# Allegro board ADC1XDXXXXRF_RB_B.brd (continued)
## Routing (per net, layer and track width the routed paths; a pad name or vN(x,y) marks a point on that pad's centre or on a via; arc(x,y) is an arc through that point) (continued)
DID-1: length 67
  TOP w0.102: U1.D10 v1(188.44,87.91) ; U5.U24 v1(136.72,87.74)
  SIG1 w0.102: v1(188.44,87.91) 188.84,87.92 189.18,87.58 189.18,82.55 185.31,78.67 144.72,78.67 136.92,86.47 136.92,87.55 v1(136.72,87.74)
  BOTTOM w0.102: R208.2 187.88,87.48 188.01,87.48 v1(188.44,87.91)
DID-2: length 65.8
  TOP w0.102: v1(133.72,88.76) 133.23,89.25 U5.T20 ; U1.C11 186.55,87.27 v1(187.19,86.63)
  SIG2 w0.102: v1(187.19,86.63) 187.19,86.27 187.91,85.55 187.91,83.47 184.11,79.68 143.26,79.68 140.33,82.6 140.33,83.19 138.36,85.16 135.79,85.16 134.12,86.83 134.12,88.36 v1(133.72,88.76)
DID-3: length 65.8
  TOP w0.102: U1.B12 185.27,86 v1(185.85,85.43) ; U5.T23 v1(136.72,88.75)
  SIG2 w0.102: v1(136.72,88.75) 136.72,88.75 137.12,88.35 137.12,86.13 137.37,85.88 139.57,85.88 139.67,85.78 139.67,84.92 139.89,84.7 140.26,84.7 140.48,84.92 140.48,85.78 140.58,85.88 141.14,85.88 141.29,85.73 141.29,83.04 143.94,80.39 180.45,80.39 180.67,80.61 180.67,81.36 180.77,81.46 180.98,81.46 181.08,81.36 181.08,80.61 181.3,80.39 181.67,80.39 181.89,80.61 181.89,81.36 181.99,81.46 182.19,81.46 182.3,81.36 182.3,80.61 182.52,80.39 182.97,80.39 185.85,83.27 v1(185.85,85.43)
DID-4: length 65.9
  TOP w0.102: U1.D12 v1(185.89,87.92) ; v1(140.63,87.88) 140.07,88.44 139.42,88.44 U5.U26
  SIG1 w0.102: v1(185.89,87.92) 185.44,87.46 185.44,83.49 185.54,83.38 186.99,83.38 187.21,83.16 187.21,82.79 186.99,82.57 185.54,82.57 185.44,82.47 185.44,81.3 184.58,80.43 184.15,80.43 183.93,80.65 183.93,81.99 183.83,82.09 183.63,82.09 183.53,81.99 183.53,80.65 183.31,80.43 145.57,80.43 142.25,83.75 142.25,87.33 141.7,87.88 v1(140.63,87.88)
DID-5: length 65.9
  TOP w0.102: v1(134.72,89.75) U5.R21 ; U1.C13 184,87.27 v1(184.64,86.63)
  SIG3 w0.102: v1(134.72,89.75) 135.12,89.35 135.12,85.33 136.1,84.35 141.16,84.35 141.87,83.64 141.87,80.94 142.43,80.38 184.16,80.38 185.34,81.55 185.34,85.6 184.64,86.29 184.64,86.3 v1(184.64,86.63)
DID-6: length 66
  TOP w0.102: v1(136.72,89.75) 136.23,90.24 U5.R23 ; v1(183.31,85.5) 182.81,86 U1.B14
  SIG3 w0.102: v1(183.31,85.5) 183.88,84.93 183.88,84.93 184.24,84.57 184.24,83.01 183.77,82.54 149.44,82.54 149.22,82.76 149.22,83.89 149.12,83.99 148.92,83.99 148.81,83.89 148.81,82.76 148.59,82.54 148.22,82.54 148,82.76 148,83.89 147.9,83.99 147.7,83.99 147.6,83.89 147.6,82.76 147.38,82.54 147,82.54 146.78,82.76 146.78,83.89 146.68,83.99 146.48,83.99 146.38,83.89 146.38,82.76 146.16,82.54 144.38,82.54 144.05,82.87 144.05,85.45 143.73,85.77 137.61,85.77 137.12,86.26 137.12,89.35 v1(136.72,89.75)
DID-7: length 65.9
  TOP w0.102: U5.R25 v1(138.72,89.75) ; v1(183.43,87.84) 182.73,88.54 U1.D14
  SIG2 w0.102: v1(138.72,89.75) 138.72,89.75 139.18,89.29 141.55,89.29 142.21,88.62 142.21,88.08 142.11,87.98 141.48,87.98 141.26,87.76 141.26,87.39 141.48,87.17 142.11,87.17 142.21,87.07 142.21,83.28 144.27,81.22 179.77,81.22 179.99,81.44 179.99,81.92 180.09,82.02 180.62,82.02 180.84,82.24 180.84,83.15 180.94,83.25 181.14,83.25 181.24,83.15 181.24,82.24 181.47,82.02 181.84,82.02 182.06,82.24 182.06,83.15 182.16,83.25 182.36,83.25 182.46,83.15 182.46,82.24 182.68,82.02 183.6,82.02 184.13,82.54 184.13,87.14 v1(183.43,87.84)
DID-8: length 66
  TOP w0.102: U1.C15 181.54,87.27 v1(182.08,86.74) ; U5.P22 135.22,91.24 v1(135.72,90.75)
  SIG1 w0.102: v1(182.08,86.74) 182.83,85.98 182.83,83.2 182.5,82.86 181.78,82.86 181.68,82.76 181.68,82.55 181.78,82.45 182.44,82.45 182.66,82.23 182.66,81.65 182.33,81.32 146.06,81.32 143.08,84.3 143.08,89.78 142.71,90.14 142.46,90.14 142.35,90.04 142.35,89.4 142.13,89.18 141.76,89.18 141.54,89.4 141.54,90.04 141.44,90.14 141.24,90.14 141.13,90.04 141.13,89.4 140.91,89.18 140.54,89.18 140.32,89.4 140.32,90.04 140.22,90.14 136.32,90.14 135.72,90.74 v1(135.72,90.75)
DID-9: length 65.9
  TOP w0.102: U1.B16 v1(179.57,85.38) ; U5.P24 v1(137.72,90.75)
  SIG1 w0.102: v1(137.72,90.75) 138.12,90.75 138.72,91.35 139.47,91.35 139.47,91.35 139.98,91.35 139.98,91.35 143.28,91.35 143.39,91.23 143.39,91.23 144.24,90.38 144.24,84.93 146.84,82.32 168.95,82.32 169.05,82.43 169.05,83.23 169.27,83.45 169.64,83.45 169.86,83.23 169.86,82.43 169.96,82.32 170.17,82.32 170.27,82.43 170.27,83.23 170.49,83.45 170.86,83.45 171.08,83.23 171.08,82.43 171.18,82.32 171.39,82.32 171.49,82.43 171.49,83.23 171.71,83.45 172.08,83.45 172.3,83.23 172.3,82.43 172.4,82.32 172.75,82.32 172.85,82.43 172.85,83.21 173.07,83.43 173.44,83.43 173.66,83.21 173.66,82.43 173.76,82.32 180.4,82.32 180.53,82.45 180.53,82.74 180.42,82.84 178.14,82.84 177.92,83.07 177.92,84.66 178.14,84.88 179.46,84.88 179.57,84.98 v1(179.57,85.38)
DID-10: length 66
  TOP w0.102: U1.C16 180.19,87.27 v1(180.85,86.62) ; U5.N20 133.23,92.25 v1(133.72,91.75)
  SIG2 w0.102: v1(133.72,91.75) 133.72,90.81 134.39,90.14 141.86,90.14 143.13,88.87 143.13,83.76 144.7,82.19 168.02,82.19 168.24,82.41 168.24,83.04 168.34,83.14 168.54,83.14 168.64,83.04 168.64,82.41 168.86,82.19 169.24,82.19 169.46,82.41 169.46,83.04 169.56,83.14 169.76,83.14 169.86,83.04 169.86,82.41 170.08,82.19 170.45,82.19 170.68,82.41 170.68,83.04 170.78,83.14 170.98,83.14 171.08,83.04 171.08,82.41 171.3,82.19 171.67,82.19 171.89,82.41 171.89,83.04 172,83.14 172.2,83.14 172.3,83.04 172.3,82.41 172.52,82.19 178.71,82.19 178.97,82.46 178.97,84.43 179.15,84.61 180.05,84.61 180.3,84.86 180.3,86.08 v1(180.85,86.62)
DID-11: length 65.9
  TOP w0.102: U5.N24 v1(137.72,91.75) ; U1.A19 v1(175.74,84.1)
  SIG3 w0.102: v1(137.72,91.75) 138.15,91.75 138.76,92.35 148.94,92.35 151.27,90.03 151.27,84.65 151.7,84.21 167.79,84.21 167.89,84.31 167.89,86.02 168.1,86.23 168.47,86.23 168.69,86.01 168.69,84.29 168.8,84.18 169.01,84.18 169.11,84.28 169.11,86.02 169.32,86.23 169.69,86.23 169.91,86.01 169.91,84.29 170.02,84.18 170.23,84.18 170.33,84.28 170.33,86.02 170.54,86.23 170.91,86.23 171.13,86.01 171.13,84.29 171.24,84.18 171.44,84.18 171.55,84.28 171.55,86.02 171.76,86.23 171.96,86.23 171.96,86.23 172.13,86.23 172.35,86.01 172.35,84.28 172.46,84.18 172.66,84.18 172.76,84.28 172.76,85.09 172.76,86.01 172.98,86.23 173.15,86.23 173.15,86.23 173.35,86.23 173.57,86.01 173.57,83.83 173.75,83.64 175.6,83.64 175.74,83.79 v1(175.74,84.1)
DQ+0: length 67
  TOP w0.102: U5.D26 v1(139.73,101.75) ; U1.W18 v1(177.01,106.96)
  SIG1 w0.102: v1(177.01,106.96) 177.44,106.53 177.74,106.53 177.88,106.67 177.88,107.08 177.23,107.73 148.54,107.73 148.4,107.6 148.4,106.87 148.17,106.63 147.22,106.63 146.95,106.36 146.95,105.31 147.11,105.14 148.24,105.14 148.46,104.92 148.46,104.55 148.24,104.32 146.9,104.32 146.79,104.21 146.79,104.01 146.88,103.92 148.24,103.92 148.46,103.7 148.46,103.33 148.24,103.11 147.48,103.11 147.37,102.99 147.37,102.74 147.06,102.43 146.28,102.43 146.06,102.65 146.06,104.05 145.96,104.15 145.76,104.15 145.65,104.05 145.65,102.4 145.43,102.18 145.06,102.18 144.84,102.4 144.84,104.05 144.74,104.15 144.54,104.15 144.43,104.05 144.43,102.4 144.21,102.18 143.84,102.18 143.62,102.4 143.62,104.05 143.52,104.15 143.32,104.15 143.22,104.05 143.22,102.04 142.99,101.82 142.57,101.82 142.35,102.04 142.35,103.55 142.25,103.65 142.05,103.65 141.95,103.55 141.95,102.29 141.61,101.95 139.93,101.95 v1(139.73,101.75)
  BOTTOM w0.102: R216.1 177.44,107.52 177.44,107.39 v1(177.01,106.96) R215.2
DQ+1: length 67.1
  TOP w0.102: U1.W19 v1(175.74,106.96) ; U5.F20 v1(133.73,99.75)
  SIG3 w0.102: v1(175.74,106.96) 175.35,106.56 172.65,106.56 172.42,106.79 172.42,107.97 172.33,108.07 172.12,108.07 172.02,107.96 172.02,106.79 171.8,106.57 171.42,106.57 171.21,106.79 171.21,107.97 171.11,108.07 170.9,108.07 170.8,107.96 170.8,106.79 170.58,106.57 170.2,106.57 169.99,106.79 169.99,107.97 169.89,108.07 169.68,108.07 169.58,107.96 169.58,106.79 169.36,106.57 169.08,106.57 168.53,106.03 168.53,96.53 167.08,95.07 164.66,95.07 163.88,95.86 155.95,95.86 155.14,96.66 155.14,99.72 154.71,100.15 136.36,100.15 135.96,99.75 v1(133.73,99.75)
  BOTTOM w0.102: v1(175.74,106.96) 176.17,107.39 176.17,107.52 R219.1
DQ+2: length 65.9
  TOP w0.102: v1(136.73,100.75) 136.22,100.25 U5.E23 ; U1.V19 176.38,106.32 v1(175.8,105.74)
  SIG2 w0.102: v1(136.73,100.75) 137.13,101.15 148.89,101.15 149.5,101.76 149.5,104.63 149.95,105.08 150.24,105.08 150.46,105.3 150.46,106.71 150.56,106.81 150.77,106.81 150.87,106.71 150.87,105.3 151.09,105.08 151.46,105.08 151.68,105.3 151.68,106.71 151.78,106.81 151.98,106.81 152.09,106.71 152.09,105.3 152.31,105.08 152.68,105.08 152.9,105.3 152.9,106.71 153,106.81 153.2,106.81 153.31,106.71 153.31,105.3 153.53,105.08 153.9,105.08 154.12,105.3 154.12,106.71 154.22,106.81 154.42,106.81 154.52,106.71 154.52,105.3 154.74,105.08 155.12,105.08 155.34,105.3 155.34,106.71 155.44,106.81 155.64,106.81 155.74,106.71 155.74,105.3 155.96,105.08 156.34,105.08 156.56,105.3 156.56,106.71 156.66,106.81 156.86,106.81 156.96,106.71 156.96,105.3 157.18,105.08 157.55,105.08 157.78,105.3 157.78,106.71 157.88,106.81 158.08,106.81 158.18,106.71 158.18,105.3 158.4,105.08 174.5,105.08 175.16,105.74 v1(175.8,105.74)
DQ+3: length 66
  TOP w0.102: U5.E25 v1(138.73,100.75) ; U1.U18 v1(178.22,104.49)
  SIG1 w0.102: v1(178.22,104.49) 177.58,104.49 177.24,104.83 176.8,104.83 176.6,104.63 176.6,104.32 176.27,103.98 173.72,103.98 173.52,104.18 173.52,107 173.24,107.28 172.82,107.28 172.6,107.06 172.6,105.61 172.5,105.51 172.3,105.51 172.19,105.61 172.19,107.06 171.97,107.28 171.6,107.28 171.38,107.06 171.38,105.61 171.28,105.51 171.08,105.51 170.97,105.61 170.97,107.06 170.75,107.28 170.38,107.28 170.16,107.06 170.16,105.61 170.06,105.51 169.86,105.51 169.76,105.61 169.76,107.06 169.53,107.28 169.16,107.28 168.94,107.06 168.94,105.61 168.84,105.51 168.64,105.51 168.54,105.61 168.54,107.06 168.32,107.28 167.94,107.28 167.72,107.06 167.72,105.61 167.62,105.51 167.42,105.51 167.32,105.61 167.32,107.06 167.1,107.28 149.25,107.28 148.79,106.82 148.79,102.04 148.54,101.79 144.01,101.79 143.58,101.36 139.33,101.36 139.01,101.03 v1(138.73,100.75)
DQ+4: length 66
  TOP w0.102: U1.U19 v1(175.75,104.43) ; U5.G19 v1(132.71,97.75)
  SIG3 w0.102: v1(132.71,97.75) 133.11,98.15 152.1,98.15 152.43,97.81 152.43,94.15 153.02,93.56 154.42,93.56 154.64,93.78 154.64,94.66 154.74,94.76 154.94,94.76 155.04,94.66 155.04,93.78 155.26,93.56 155.89,93.56 156.11,93.78 156.11,94.5 156.21,94.6 156.41,94.6 156.51,94.5 156.51,93.78 156.74,93.56 157.11,93.56 157.33,93.78 157.33,94.5 157.43,94.6 157.63,94.6 157.73,94.5 157.73,93.78 157.95,93.56 158.33,93.56 158.55,93.78 158.55,94.5 158.65,94.6 158.85,94.6 158.95,94.5 158.95,93.78 159.17,93.56 169.47,93.56 170,94.1 170,103.5 170.56,104.05 175.38,104.05 v1(175.75,104.43)
DQ+5: length 65.9
  TOP w0.102: U5.F24 137.22,99.25 v1(137.73,99.75) ; U1.T19 v1(175.76,103.17)
  SIG2 w0.102: v1(175.76,103.17) 175.1,103.17 174.69,102.76 174.69,102.76 174.47,102.54 173.89,102.54 173.62,102.81 173.62,104.01 173.28,104.35 158.58,104.35 158.48,104.25 158.48,102.64 158.26,102.42 157.88,102.42 157.66,102.64 157.66,104.25 157.56,104.35 157.36,104.35 157.26,104.25 157.26,102.64 157.04,102.42 156.67,102.42 156.44,102.64 156.44,104.25 156.34,104.35 156.14,104.35 156.04,104.25 156.04,102.64 155.82,102.42 155.45,102.42 155.23,102.64 155.23,104.25 155.12,104.35 154.92,104.35 154.82,104.25 154.82,102.64 154.6,102.42 154.23,102.42 154.01,102.64 154.01,104.25 153.9,104.35 153.7,104.35 153.6,104.25 153.6,102.64 153.38,102.42 153.01,102.42 152.79,102.64 152.79,104.25 152.69,104.35 152.48,104.35 152.38,104.25 152.38,102.64 152.16,102.42 151.79,102.42 151.57,102.64 151.57,104.25 151.47,104.35 151.12,104.35 150.49,103.72 150.49,100.8 149.84,100.15 138.13,100.15 v1(137.73,99.75)
DQ+6: length 65.9
  TOP w0.102: v1(177.03,101.89) 177.65,102.51 U1.R18 ; U5.F26 v1(139.73,99.75)
  SIG1 w0.102: v1(177.03,101.89) 176.52,102.4 173.78,102.4 172.82,103.36 172.56,103.36 172.34,103.58 172.34,104.65 172.24,104.75 172.04,104.75 171.94,104.65 171.94,103.58 171.72,103.36 171.35,103.36 171.12,103.58 171.12,104.65 171.02,104.75 170.82,104.75 170.72,104.65 170.72,103.58 170.5,103.36 170.13,103.36 169.91,103.58 169.91,104.65 169.8,104.75 169.6,104.75 169.5,104.65 169.5,103.58 169.28,103.36 168.91,103.36 168.69,103.58 168.69,104.65 168.58,104.75 168.38,104.75 168.28,104.65 168.28,103.58 168.06,103.36 167.69,103.36 167.47,103.58 167.47,104.65 167.37,104.75 167.16,104.75 167.06,104.65 167.06,103.58 166.84,103.36 166.22,103.36 165.84,103.74 165.84,106.19 165.6,106.43 165.37,106.43 165.26,106.32 165.26,104.9 165.04,104.68 164.67,104.68 164.45,104.9 164.45,106.32 164.35,106.43 164.15,106.43 164.05,106.32 164.05,104.9 163.83,104.68 163.45,104.68 163.23,104.9 163.23,106.32 163.13,106.43 150.13,106.43 149.94,106.24 149.94,101.68 149.35,101.09 145.16,101.09 144.22,100.14 140.12,100.14 v1(139.73,99.75)
DQ+7: length 65.9
  TOP w0.102: v1(135.71,97.75) 135.22,98.24 U5.G22 ; v1(178.3,100.63) 178.92,101.24 U1.P17
  SIG2 w0.102: v1(178.3,100.63) 177.51,101.42 173.84,101.42 173.51,101.09 173.51,100.57 173.3,100.36 170.52,100.36 170.17,100.71 170.17,103.38 169.73,103.82 159.56,103.82 159.11,103.36 159.11,102.36 158.79,102.05 151.93,102.05 151.46,101.58 151.46,99.8 151.2,99.54 148.25,99.54 148.03,99.32 148.03,97.91 147.93,97.81 147.73,97.81 147.63,97.91 147.63,99.32 147.41,99.54 147.03,99.54 146.81,99.32 146.81,97.91 146.71,97.81 146.51,97.81 146.41,97.91 146.41,99.32 146.19,99.54 145.82,99.54 145.59,99.32 145.59,97.91 145.49,97.81 145.29,97.81 145.19,97.91 145.19,99.32 144.97,99.54 144.6,99.54 144.38,99.32 144.38,97.91 144.27,97.81 144.07,97.81 143.97,97.91 143.97,99.32 143.75,99.54 143.32,99.54 142.93,99.16 142.93,97.63 142.66,97.35 136.11,97.35 v1(135.71,97.75)
DQ+8: length 66
  TOP w0.102: U1.P19 176.38,101.24 v1(175.74,100.61) ; U5.G24 v1(137.73,98.75)
  SIG1 w0.102: v1(175.74,100.61) 175.07,100.61 174.43,99.97 170.65,99.97 170.28,100.34 170.28,102.11 170.17,102.21 169.97,102.21 169.87,102.11 169.87,100.51 169.87,100.34 169.65,100.12 169.28,100.12 169.06,100.34 169.06,102.11 168.96,102.21 168.75,102.21 168.65,102.11 168.65,100.51 168.65,100.51 168.65,100.34 168.44,100.12 168.06,100.12 167.84,100.34 167.84,102.11 167.74,102.21 167.53,102.21 167.43,102.11 167.43,100.51 167.43,100.34 167.22,100.12 167.05,100.12 166.84,100.12 166.62,100.34 166.62,102.11 166.52,102.21 166.31,102.21 166.22,102.12 166.22,100.34 166,100.12 165.5,100.12 165.28,100.34 165.28,103.73 165.03,103.98 162.9,103.98 162.59,104.29 162.59,105.58 162.4,105.77 151.02,105.77 150.76,105.5 150.76,100.69 150.19,100.12 145.16,100.12 144.54,99.51 141.03,99.51 140.63,99.1 138.08,99.1 v1(137.73,98.75)
DQ+9: length 66
  TOP w0.102: U1.N17 178.92,99.97 v1(178.35,99.4) ; v1(142.09,98.75) 142.09,98.75 141.66,98.32 139.3,98.32 U5.G26
  SIG1 w0.102: v1(178.35,99.4) 177.7,99.4 177,98.71 177,98.71 166.92,98.71 166.08,99.56 164.94,99.56 164.72,99.78 164.72,103.25 164.62,103.35 164.42,103.35 164.32,103.25 164.32,99.78 164.09,99.56 163.72,99.56 163.5,99.78 163.5,103.25 163.4,103.35 163.2,103.35 163.1,103.25 163.1,99.78 162.88,99.56 162.25,99.56 162.03,99.78 162.03,104.86 161.93,104.96 151.59,104.96 151.51,104.88 151.51,99.8 151.27,99.56 145.59,99.56 145.05,99.02 142.36,99.02 142.09,98.75 v1(142.09,98.75)
DQ+10: length 65.9
  TOP w0.102: U1.N19 176.38,99.97 v1(175.8,99.39) ; U5.H22 v1(134.73,96.75)
  SIG3 w0.102: v1(175.8,99.39) 175.17,99.39 174.75,98.98 172.95,98.98 172.61,98.64 172.61,92.75 171.74,91.88 159.85,91.88 159.74,91.78 159.74,90.63 159.52,90.41 159.15,90.41 158.93,90.63 158.93,91.78 158.83,91.88 158.63,91.88 158.53,91.78 158.53,90.63 158.3,90.41 157.93,90.41 157.71,90.63 157.71,91.78 157.61,91.88 157.09,91.88 156.99,91.78 156.99,90.67 156.77,90.45 156.4,90.45 156.18,90.67 156.18,91.78 156.08,91.88 155.87,91.88 155.77,91.78 155.77,90.67 155.55,90.45 155.18,90.45 154.96,90.67 154.96,91.78 154.86,91.88 154.66,91.88 154.55,91.78 154.55,90.67 154.33,90.45 153.96,90.45 153.74,90.67 153.74,91.78 153.64,91.88 151.19,91.88 150.83,92.24 150.83,95.91 150.6,96.15 139.89,96.15 139.89,96.15 139.56,96.15 139.56,96.15 138.9,96.15 138.9,96.15 138.56,96.15 138.56,96.15 137.89,96.15 137.89,96.15 137.56,96.15 137.56,96.15 136.89,96.15 136.89,96.15 136.56,96.15 136.56,96.15 135.33,96.15 v1(134.73,96.75)
DQ+11: length 66
  TOP w0.102: U1.M18 177.65,98.7 v1(177.05,98.1) ; U5.H24 v1(137.73,97.75)
  SIG1 w0.102: v1(177.05,98.1) 176.48,98.1 175.83,97.45 168.18,97.45 167.99,97.26 167.99,95.41 167.74,95.17 161.8,95.17 161.26,95.71 161.26,104.05 161.07,104.23 160.82,104.23 160.72,104.13 160.72,103.44 160.5,103.22 160.13,103.22 159.91,103.44 159.91,104.13 159.8,104.23 159.6,104.23 159.5,104.13 159.5,103.44 159.28,103.22 158.91,103.22 158.69,103.44 158.69,104.13 158.58,104.23 158.38,104.23 158.28,104.13 158.28,103.44 158.06,103.22 157.69,103.22 157.47,103.44 157.47,104.13 157.37,104.23 157.16,104.23 157.06,104.13 157.06,103.44 156.84,103.22 156.47,103.22 156.25,103.44 156.25,104.13 156.15,104.23 155.94,104.23 155.84,104.13 155.84,103.44 155.62,103.22 155.25,103.22 155.03,103.44 155.03,104.13 154.93,104.23 152.4,104.23 152.22,104.05 152.22,98.82 151.54,98.14 140.83,98.14 140.57,98.4 139.02,98.4 138.77,98.16 138.13,98.16 v1(137.73,97.75)
DQ-0: length 67.1
  TOP w0.102: U1.V17 v1(178.28,106.96) ; U5.D25 v1(138.73,101.75)
  SIG1 w0.102: v1(178.28,106.96) 178.28,106.96 177.32,107.93 148.45,107.93 148.2,107.68 148.2,106.95 148.08,106.83 147.13,106.83 146.74,106.45 146.74,105.22 147.03,104.93 148.16,104.93 148.26,104.83 148.26,104.63 148.16,104.53 146.81,104.53 146.58,104.3 146.58,103.93 146.79,103.72 148.16,103.72 148.26,103.61 148.26,103.41 148.16,103.31 147.4,103.31 147.17,103.08 147.17,102.82 146.97,102.63 146.36,102.63 146.26,102.73 146.26,104.13 146.04,104.35 145.67,104.35 145.45,104.13 145.45,102.49 145.35,102.39 145.15,102.39 145.04,102.49 145.04,104.13 144.82,104.35 144.45,104.35 144.23,104.13 144.23,102.49 144.13,102.39 143.93,102.39 143.82,102.49 143.82,104.13 143.6,104.35 143.23,104.35 143.01,104.13 143.01,102.12 142.91,102.02 142.66,102.02 142.55,102.12 142.55,103.64 142.33,103.86 141.96,103.86 141.74,103.64 141.74,102.37 141.52,102.15 139.27,102.15 138.87,101.75 v1(138.73,101.75)
  BOTTOM w0.102: R217.2 178.71,107.52 178.71,107.39 v1(178.28,106.96) R215.1
DQ-1: length 67.1
  TOP w0.102: U1.W20 v1(174.47,106.96) ; v1(132.73,99.75) 133.22,100.24 U5.E20
  SIG3 w0.102: v1(174.47,106.96) 174.29,106.77 174.28,106.77 172.74,106.77 172.63,106.87 172.63,108.05 172.41,108.27 172.04,108.27 171.81,108.04 171.81,106.88 171.71,106.77 171.51,106.77 171.41,106.87 171.41,108.05 171.19,108.27 170.82,108.27 170.59,108.04 170.59,106.88 170.49,106.77 170.29,106.77 170.19,106.87 170.19,108.05 169.97,108.27 169.6,108.27 169.37,108.04 169.37,106.88 169.27,106.77 168.99,106.77 168.33,106.11 168.33,96.61 166.99,95.28 164.74,95.28 163.96,96.06 156.03,96.06 155.34,96.75 155.34,99.8 154.79,100.36 136.27,100.36 135.87,99.96 134.12,99.96 133.92,100.16 133.49,100.16 133.09,99.75 v1(132.73,99.75)
  BOTTOM w0.102: R218.1 v1(174.47,106.96) 174.9,107.39 174.9,107.52 R220.2
DQ-2: length 65.9
  TOP w0.102: U5.E22 v1(135.73,100.75) ; U1.V20 175.11,106.32 v1(174.51,105.73)
  SIG2 w0.102: v1(135.73,100.75) 136.11,100.75 136.53,101.18 136.86,101.18 137.04,101.36 148.81,101.36 149.3,101.85 149.3,104.72 149.86,105.28 150.16,105.28 150.26,105.38 150.26,106.79 150.48,107.01 150.85,107.01 151.07,106.79 151.07,105.38 151.17,105.28 151.37,105.28 151.48,105.38 151.48,106.79 151.7,107.01 152.07,107.01 152.29,106.79 152.29,105.38 152.39,105.28 152.59,105.28 152.7,105.38 152.7,106.79 152.92,107.01 153.29,107.01 153.51,106.79 153.51,105.38 153.61,105.28 153.81,105.28 153.91,105.38 153.91,106.79 154.14,107.01 154.51,107.01 154.73,106.79 154.73,105.38 154.83,105.28 155.03,105.28 155.13,105.38 155.13,106.79 155.35,107.01 155.73,107.01 155.95,106.79 155.95,105.38 156.05,105.28 156.25,105.28 156.35,105.38 156.35,106.79 156.57,107.01 156.95,107.01 157.17,106.79 157.17,105.38 157.27,105.28 157.47,105.28 157.57,105.38 157.57,106.79 157.79,107.01 158.16,107.01 158.39,106.79 158.39,105.38 158.49,105.28 174.41,105.28 174.51,105.39 v1(174.51,105.73)
DQ-3: length 65.9
  TOP w0.102: U5.E24 v1(137.73,100.75) ; U1.T18 v1(177,104.43)
  SIG1 w0.102: v1(177,104.43) 176.35,103.78 173.63,103.78 173.31,104.1 173.31,106.92 173.16,107.07 172.9,107.07 172.8,106.97 172.8,105.53 172.58,105.31 172.21,105.31 171.99,105.53 171.99,106.97 171.89,107.07 171.69,107.07 171.58,106.97 171.58,105.53 171.36,105.31 170.99,105.31 170.77,105.53 170.77,106.97 170.67,107.07 170.47,107.07 170.36,106.97 170.36,105.53 170.14,105.31 169.77,105.31 169.55,105.53 169.55,106.97 169.45,107.07 169.25,107.07 169.15,106.97 169.15,105.53 168.93,105.31 168.55,105.31 168.33,105.53 168.33,106.97 168.23,107.07 168.03,107.07 167.93,106.97 167.93,105.53 167.71,105.31 167.33,105.31 167.11,105.53 167.11,106.97 167.01,107.07 149.34,107.07 149,106.73 149,101.95 148.63,101.58 144.09,101.58 143.67,101.15 139.42,101.15 139.16,100.89 139.16,100.61 138.9,100.36 138.57,100.36 138.17,100.75 v1(137.73,100.75)
DQ-4: length 66
  TOP w0.102: U5.F19 132.22,99.25 v1(132.72,98.75) ; U1.U20 175.11,105.05 v1(174.52,104.46)
  SIG3 w0.102: v1(132.72,98.75) 132.43,98.75 132.18,98.51 132.18,98.32 132.34,98.16 132.83,98.16 133.03,98.35 152.18,98.35 152.64,97.9 152.64,94.23 153.1,93.77 154.33,93.77 154.43,93.87 154.43,94.75 154.66,94.97 155.03,94.97 155.25,94.75 155.25,93.87 155.35,93.77 155.8,93.77 155.9,93.87 155.9,94.59 156.13,94.81 156.5,94.81 156.72,94.59 156.72,93.87 156.82,93.77 157.02,93.77 157.12,93.87 157.12,94.59 157.34,94.81 157.72,94.81 157.94,94.59 157.94,93.87 158.04,93.77 158.24,93.77 158.34,93.87 158.34,94.59 158.56,94.81 158.94,94.81 159.16,94.59 159.16,93.87 159.26,93.77 169.38,93.77 169.8,94.18 169.8,103.58 170.47,104.26 174.31,104.26 v1(174.52,104.46)
DQ-5: length 65.9
  TOP w0.102: U5.F23 v1(136.73,99.75) ; v1(174.49,103.17) 175.11,103.78 U1.T20
  SIG2 w0.102: v1(136.73,99.75) 137.13,99.75 137.73,100.36 149.76,100.36 150.29,100.89 150.29,103.81 151.04,104.56 151.55,104.56 151.77,104.34 151.77,102.72 151.87,102.62 152.08,102.62 152.18,102.72 152.18,104.34 152.4,104.56 152.77,104.56 152.99,104.34 152.99,102.72 153.09,102.62 153.3,102.62 153.4,102.72 153.4,104.34 153.62,104.56 153.99,104.56 154.21,104.34 154.21,102.72 154.31,102.62 154.51,102.62 154.62,102.72 154.62,104.34 154.84,104.56 155.21,104.56 155.43,104.34 155.43,102.72 155.53,102.62 155.73,102.62 155.84,102.72 155.84,104.34 156.06,104.56 156.43,104.56 156.65,104.34 156.65,102.72 156.75,102.62 156.95,102.62 157.05,102.72 157.05,104.34 157.28,104.56 157.65,104.56 157.87,104.34 157.87,102.72 157.97,102.62 158.17,102.62 158.27,102.72 158.27,104.34 158.49,104.56 173.36,104.56 173.82,104.1 173.82,102.89 173.97,102.74 174.38,102.74 174.49,102.85 v1(174.49,103.17)
DQ-6: length 65.9
  TOP w0.102: U5.E26 v1(139.73,100.75) ; v1(176.99,103.13) 176.99,103.12 176.38,102.51 U1.R19
  SIG1 w0.102: v1(176.99,103.13) 176.46,102.6 173.86,102.6 172.9,103.56 172.65,103.56 172.55,103.66 172.55,104.73 172.33,104.95 171.95,104.95 171.73,104.73 171.73,103.66 171.63,103.56 171.43,103.56 171.33,103.66 171.33,104.73 171.11,104.95 170.74,104.95 170.52,104.73 170.52,103.66 170.41,103.56 170.21,103.56 170.11,103.66 170.11,104.73 169.89,104.95 169.52,104.95 169.3,104.73 169.3,103.66 169.19,103.56 168.99,103.56 168.89,103.66 168.89,104.73 168.67,104.95 168.3,104.95 168.08,104.73 168.08,103.66 167.98,103.56 167.77,103.56 167.67,103.66 167.67,104.73 167.45,104.95 167.08,104.95 166.86,104.73 166.86,103.66 166.76,103.56 166.3,103.56 166.04,103.82 166.04,106.27 165.68,106.63 165.28,106.63 165.06,106.41 165.06,104.98 164.96,104.88 164.76,104.88 164.66,104.98 164.66,106.41 164.43,106.63 164.06,106.63 163.84,106.41 163.84,104.98 163.74,104.88 163.54,104.88 163.44,104.98 163.44,106.41 163.22,106.63 150.04,106.63 149.74,106.32 149.74,101.76 149.27,101.29 145.08,101.29 144.13,100.35 140.14,100.35 v1(139.73,100.75)
DQ-7: length 65.9
  TOP w0.102: U1.P18 177.64,101.24 v1(177.01,100.62) ; v1(134.72,97.75) 134.22,98.24 U5.G21
  SIG2 w0.102: v1(134.72,97.75) 135.32,97.15 142.74,97.15 143.14,97.55 143.14,99.07 143.4,99.34 143.66,99.34 143.77,99.24 143.77,97.83 143.99,97.6 144.36,97.6 144.58,97.83 144.58,99.24 144.68,99.34 144.88,99.34 144.98,99.24 144.98,97.83 145.21,97.6 145.58,97.6 145.8,97.83 145.8,99.24 145.9,99.34 146.1,99.34 146.2,99.24 146.2,97.83 146.42,97.6 146.8,97.6 147.02,97.83 147.02,99.24 147.12,99.34 147.32,99.34 147.42,99.24 147.42,97.83 147.64,97.6 148.02,97.6 148.24,97.83 148.24,99.24 148.34,99.34 151.28,99.34 151.66,99.72 151.66,101.5 152.01,101.85 158.88,101.85 159.31,102.28 159.31,103.28 159.65,103.61 169.65,103.61 169.97,103.29 169.97,100.62 170.44,100.16 173.39,100.16 173.71,100.48 173.71,101.01 173.92,101.21 176.8,101.21 177.01,101.01 v1(177.01,100.62)
DQ-8: length 65.9
  TOP w0.102: v1(174.48,100.62) 175.11,101.24 U1.P20 ; U5.G23 v1(136.73,98.75)
  SIG1 w0.102: v1(136.73,98.75) 137.09,98.75 137.65,99.31 140.54,99.31 140.95,99.71 144.46,99.71 145.07,100.32 150.11,100.32 150.55,100.77 150.55,105.59 150.94,105.97 162.48,105.97 162.79,105.66 162.79,104.38 162.98,104.19 165.11,104.19 165.48,103.81 165.48,100.43 165.59,100.32 165.91,100.32 166,100.42 166,102.19 166.23,102.42 166.6,102.42 166.83,102.18 166.83,102.04 166.83,102.04 166.83,100.43 166.93,100.32 167.13,100.32 167.23,100.42 167.23,102.19 167.45,102.42 167.82,102.42 168.05,102.19 168.05,100.43 168.15,100.32 168.35,100.32 168.45,100.42 168.45,102.19 168.67,102.42 169.04,102.42 169.27,102.19 169.27,100.43 169.37,100.32 169.57,100.32 169.67,100.42 169.67,102.19 169.89,102.42 170.26,102.42 170.49,102.19 170.49,102.04 170.48,102.04 170.48,100.43 170.74,100.18 174.34,100.18 174.48,100.31 v1(174.48,100.62)
DQ-9: length 65.9
  TOP w0.102: U5.G25 138.54,98.24 138.93,98.63 141.11,98.63 v1(141.26,98.78) ; v1(177.08,99.41) 177.65,99.97 U1.N18
  SIG1 w0.102: v1(177.08,99.41) 177.08,99.08 176.91,98.92 167.01,98.92 166.16,99.76 165.03,99.76 164.92,99.86 164.92,103.33 164.7,103.55 164.33,103.55 164.11,103.33 164.11,99.86 164.01,99.76 163.81,99.76 163.71,99.86 163.71,103.33 163.49,103.55 163.11,103.55 162.89,103.33 162.89,99.86 162.79,99.76 162.34,99.76 162.23,99.86 162.23,104.94 162.01,105.16 151.51,105.16 151.31,104.96 151.31,99.88 151.19,99.76 145.5,99.76 144.97,99.23 141.74,99.23 141.29,98.78 v1(141.26,98.78)
DQ-10: length 66
  TOP w0.102: U1.N20 175.1,99.97 v1(174.53,99.4) ; v1(133.73,96.75) 134.22,97.24 U5.H21
  SIG3 w0.102: v1(133.73,96.75) 134.14,96.75 134.56,97.18 134.91,97.18 135.13,96.96 135.13,96.64 135.42,96.35 136.47,96.35 136.47,96.35 136.97,96.35 136.98,96.35 137.47,96.35 137.47,96.35 137.97,96.35 137.98,96.35 138.48,96.35 138.48,96.35 138.98,96.35 138.98,96.35 139.47,96.35 139.48,96.35 139.98,96.35 139.98,96.35 150.68,96.35 151.03,96 151.03,92.32 151.28,92.08 153.72,92.08 153.94,91.86 153.94,90.75 154.05,90.65 154.25,90.65 154.35,90.75 154.35,91.86 154.57,92.08 154.94,92.08 155.16,91.86 155.16,90.75 155.27,90.65 155.47,90.65 155.57,90.75 155.57,91.86 155.79,92.08 156.16,92.08 156.38,91.86 156.38,90.75 156.48,90.65 156.69,90.65 156.79,90.75 156.79,91.86 157.01,92.08 157.7,92.08 157.92,91.86 157.92,90.72 158.02,90.61 158.22,90.61 158.32,90.72 158.32,91.86 158.54,92.08 158.91,92.08 159.14,91.86 159.14,90.72 159.24,90.61 159.44,90.61 159.54,90.72 159.54,91.86 159.76,92.08 171.66,92.08 172.41,92.83 172.41,98.73 172.86,99.18 174.31,99.18 v1(174.53,99.4)
DQ-11: length 65.9
  TOP w0.102: v1(136.72,97.75) 136.22,97.25 U5.H23 ; v1(175.78,98.1) 176.38,98.7 U1.M19
  SIG1 w0.102: v1(175.78,98.1) 175.78,97.81 175.62,97.66 168.09,97.66 167.78,97.35 167.78,95.49 167.66,95.37 161.89,95.37 161.46,95.8 161.46,103.96 161.46,104.13 161.16,104.43 160.74,104.43 160.51,104.21 160.51,103.53 160.41,103.42 160.21,103.42 160.11,103.53 160.11,104.21 159.89,104.43 159.52,104.43 159.3,104.21 159.3,103.53 159.19,103.42 158.99,103.42 158.89,103.53 158.89,104.21 158.67,104.43 158.3,104.43 158.08,104.21 158.08,103.53 157.97,103.42 157.77,103.42 157.67,103.53 157.67,104.21 157.45,104.43 157.08,104.43 156.86,104.21 156.86,103.53 156.76,103.42 156.55,103.42 156.45,103.53 156.45,104.21 156.23,104.43 155.86,104.43 155.64,104.21 155.64,103.53 155.54,103.42 155.33,103.42 155.23,103.53 155.23,104.21 155.01,104.43 152.32,104.43 152.02,104.13 152.02,103.97 152.02,98.9 151.46,98.35 140.91,98.35 140.65,98.61 138.93,98.61 138.69,98.36 138.05,98.36 137.88,98.2 137.46,98.2 137.02,97.75 v1(136.72,97.75)
DQD+0: length 67
  TOP w0.102: U1.Y10 187.88,108.86 v1(188.48,109.46) ; U5.A20 133.22,104.26 v1(133.72,104.76)
  SIG1 w0.102: v1(133.72,104.76) 133.28,104.76 132.92,105.12 132.92,106.13 139.69,112.91 186.23,112.91 188.97,110.16 188.97,108.93 188.89,108.85 188.66,108.85 188.48,109.02 v1(188.48,109.46)
  BOTTOM w0.102: R222.1 187.88,109.93 188.01,109.93 v1(188.48,109.46) 188.48,109.39 R221.2
DQD+1: length 67
  TOP w0.102: U5.A22 135.22,104.26 v1(135.72,104.76) ; U1.V10 v1(188.44,106.88)
  SIG1 w0.102: v1(135.72,104.76) 135.29,104.76 134.92,105.12 134.92,105.56 134.7,105.78 134.58,105.78 134.48,105.88 134.48,106.09 134.58,106.19 134.7,106.19 134.92,106.41 134.92,106.86 140.22,112.16 185.62,112.16 187.87,109.9 187.87,108.03 189.01,106.89 189.01,106.55 188.67,106.21 188.53,106.21 188.44,106.3 v1(188.44,106.88)
  BOTTOM w0.102: R225.1 187.88,107.39 187.93,107.39 v1(188.44,106.88)
DQD+2: length 65.9
  TOP w0.102: U5.A24 v1(137.73,104.76) ; v1(186.93,108.26) 186.93,107.76 186.77,107.59 U1.W11
  SIG1 w0.102: v1(137.73,104.76) 137.32,104.76 137.09,104.99 137.09,105.46 137.19,105.56 139.69,105.56 139.91,105.78 139.91,106.15 139.69,106.37 137.19,106.37 137.09,106.47 137.09,107.63 141.01,111.56 185.21,111.56 187.34,109.43 187.34,107.68 187.25,107.59 187.04,107.59 186.93,107.7 v1(186.93,108.26)
DQD+3: length 65.8
  TOP w0.102: v1(185.89,109.48) 185.27,108.86 U1.Y12 ; U5.B24 v1(137.73,103.76)
  SIG1 w0.102: v1(185.89,109.48) 185.43,109.02 185.43,108.68 185.53,108.58 185.96,108.58 186.56,109.17 186.56,109.46 185.15,110.87 141.54,110.87 140.62,109.95 140.62,108.78 140.4,108.56 138.99,108.56 138.88,108.46 138.88,108.25 138.99,108.15 140.5,108.15 140.72,107.93 140.72,107.56 140.5,107.34 138.99,107.34 138.88,107.24 138.88,107.03 138.99,106.93 140.4,106.93 140.62,106.71 140.62,105.44 139.34,104.16 137.83,104.16 137.73,104.06 v1(137.73,103.76)
DQD+4: length 65.9
  TOP w0.102: v1(132.72,102.77) 133.22,102.26 U5.C20 ; U1.V12 185.28,106.32 v1(185.86,106.91)
  SIG2 w0.102: v1(132.72,102.77) 132.72,102.89 132.12,103.49 132.12,105.21 139.35,112.45 183.87,112.45 186.53,109.79 186.53,107.58 v1(185.86,106.91)
DQD+5: length 66
  TOP w0.102: v1(184.62,108.22) 184,107.59 U1.W13 ; U5.C21 v1(133.71,102.76)
  SIG2 w0.102: v1(184.62,108.22) 184.62,110.32 183.06,111.88 140.51,111.88 139.78,111.15 139.78,107.38 139.47,107.08 139.01,107.08 138.91,107.18 138.91,108.27 138.69,108.49 138.32,108.49 138.09,108.27 138.09,107.18 137.99,107.08 135,107.08 133.12,105.19 133.12,103.65 133.71,103.06 v1(133.71,102.76)
DQD+6: length 65.9
  TOP w0.102: v1(139.79,102.82) 139.79,102.82 U5.C26 ; U1.Y14 v1(182.11,109.48)
  SIG1 w0.102: v1(182.11,109.48) 182.11,108.87 182.01,108.77 182.01,108.77 181.65,108.41 181.65,107.98 181.35,107.69 179.89,107.69 178.6,108.98 147.85,108.98 147.56,108.69 147.56,107.78 147.32,107.54 146.28,107.54 146.06,107.32 146.06,104.99 145.96,104.88 145.76,104.88 145.65,104.99 145.65,107.43 145.43,107.66 145.06,107.66 144.84,107.43 144.84,104.99 144.74,104.88 144.54,104.88 144.44,104.99 144.44,107.43 144.21,107.66 143.84,107.66 143.62,107.43 143.62,104.99 143.52,104.88 143.32,104.88 143.22,104.99 143.22,107.43 143,107.66 142.57,107.66 142.27,107.35 142.27,104.89 140.21,102.82 v1(139.79,102.82)
DQD+7: length 65.8
  TOP w0.102: v1(182.1,106.94) 182.72,106.32 U1.V14 ; U5.D20 v1(133.73,101.75)
  SIG2 w0.102: v1(133.73,101.75) 133.3,101.75 133.24,101.82 133.24,101.98 133.42,102.15 134.02,102.15 134.32,102.46 134.32,105.03 135.15,105.86 139.9,105.86 140.9,106.86 140.9,110.29 141.59,110.98 142.17,110.98 142.28,110.88 142.28,110.55 142.5,110.33 142.87,110.33 143.09,110.55 143.09,110.88 143.19,110.98 181.95,110.98 183.34,109.59 183.34,107.21 182.35,106.23 182.19,106.23 182.1,106.32 v1(182.1,106.94)
DQD+8: length 65.9
  TOP w0.102: v1(135.73,101.75) 135.22,101.24 U5.D22 ; v1(180.9,108.16) 181.46,107.6 U1.W15
  SIG2 w0.102: v1(135.73,101.75) 135.73,102.19 136.13,102.59 136.13,102.86 136.43,103.15 139.28,103.15 139.49,103.37 142.93,103.37 143.15,103.59 143.15,105.68 143.26,105.78 143.46,105.78 143.56,105.68 143.56,103.59 143.78,103.37 144.15,103.37 144.37,103.59 144.37,105.68 144.48,105.78 144.68,105.78 144.78,105.68 144.78,103.59 145,103.37 146.29,103.37 147.18,104.25 147.18,108.07 147.84,108.73 182.39,108.73 182.68,108.44 182.68,107.84 182.48,107.63 181.1,107.63 181,107.73 181,108.06 v1(180.9,108.16)
DQD+9: length 65.9
  TOP w0.102: U5.D23 136.22,101.25 v1(136.73,101.75) ; U1.Y16 180.19,109.95 v1(179.81,110.32)
  SIG1 w0.102: v1(179.81,110.32) 179.62,110.13 146.9,110.13 146.69,109.93 146.69,108.41 146.59,108.31 146.39,108.31 146.29,108.41 146.29,109.93 146.07,110.15 145.7,110.15 145.47,109.93 145.47,108.41 145.37,108.31 145.17,108.31 145.07,108.41 145.07,109.93 144.85,110.15 144.48,110.15 144.26,109.93 144.26,108.41 144.15,108.31 143.95,108.31 143.85,108.41 143.85,109.93 143.63,110.15 143.26,110.15 143.04,109.93 143.04,108.41 142.93,108.31 142.73,108.31 142.63,108.41 142.63,109.93 142.41,110.15 142,110.15 141.38,109.53 141.38,105.17 140.2,103.99 139.9,103.99 139.26,103.36 137.26,103.36 137.06,103.16 136.55,103.16 136.33,102.95 136.33,102.59 136.73,102.2 v1(136.73,101.75)
DQD+10: length 65.9
  TOP w0.102: v1(179.51,107) 178.92,107.59 U1.W17 ; U5.D24 137.22,101.25 v1(137.73,101.75)
  SIG2 w0.102: v1(179.51,107) 179.51,106.3 179.59,106.23 179.81,106.23 180.09,106.52 180.09,107.59 179.88,107.81 173.68,107.81 173.58,107.7 173.58,106.4 173.36,106.18 172.99,106.18 172.77,106.4 172.77,107.7 172.67,107.81 172.46,107.81 172.36,107.7 172.36,106.4 172.14,106.18 171.77,106.18 171.55,106.4 171.55,107.7 171.45,107.81 171.25,107.81 171.14,107.7 171.14,106.4 170.92,106.18 170.55,106.18 170.33,106.4 170.33,107.7 170.23,107.81 170.03,107.81 169.92,107.7 169.92,106.4 169.7,106.18 169.33,106.18 169.11,106.4 169.11,107.7 169.01,107.81 168.81,107.81 168.71,107.7 168.71,106.4 168.49,106.18 168.11,106.18 167.89,106.4 167.89,107.7 167.79,107.81 148.98,107.81 148.39,107.22 148.39,102.89 147.65,102.15 138.13,102.15 v1(137.73,101.75)
DQD+11: length 65.9
  TOP w0.102: v1(178.27,109.49) 178.27,109.49 U1.Y18 ; U5.E21 v1(134.73,100.75)
  SIG2 w0.102: v1(134.73,100.75) 134.73,101.16 134.43,101.46 134.43,101.46 134.33,101.57 134.33,101.96 134.53,102.17 134.53,102.17 134.67,102.31 134.67,102.88 136.16,104.36 141.57,104.36 141.92,104.72 141.92,108.64 143.8,110.52 144.22,110.52 144.44,110.3 144.44,107.37 144.54,107.27 144.74,107.27 144.85,107.37 144.85,110.3 145.07,110.52 145.44,110.52 145.66,110.3 145.66,107.37 145.76,107.27 145.96,107.27 146.07,107.37 146.07,110.3 146.29,110.52 177.53,110.52 178.27,109.77 v1(178.27,109.49)
DQD-0: length 67
  TOP w0.102: v1(188.49,108.27) 187.82,107.59 U1.W10 ; v1(132.72,104.76) 132.22,104.26 U5.A19
  SIG1 w0.102: v1(132.72,104.76) 132.72,106.22 139.61,113.11 186.31,113.11 189.17,110.25 189.17,108.85 188.97,108.64 188.87,108.64 v1(188.49,108.27)
  BOTTOM w0.102: R223.2 188.85,108.51 188.65,108.51 R221.1 v1(188.49,108.27)
DQD-1: length 67
  TOP w0.102: U5.A21 134.22,104.26 v1(134.72,104.76) ; U1.U10 v1(188.44,105.69)
  SIG1 w0.102: v1(188.44,105.69) 188.76,106.01 188.76,106.01 189.21,106.46 189.21,106.98 188.07,108.12 188.07,109.99 185.7,112.36 140.14,112.36 134.72,106.94 134.72,106.49 134.62,106.39 134.5,106.39 134.28,106.17 134.28,105.8 134.5,105.58 134.62,105.58 134.72,105.48 v1(134.72,104.76)
  BOTTOM w0.102: R226.2 189,106.12 188.79,106.12 R224.1 v1(188.44,105.69)
DQD-2: length 65.9
  TOP w0.102: U1.V11 186.54,106.32 v1(187.15,106.94) ; U5.A23 v1(136.73,104.76)
  SIG1 w0.102: v1(136.73,104.76) 136.88,104.91 136.88,105.54 137.1,105.76 139.6,105.76 139.71,105.86 139.71,106.07 139.6,106.17 137.1,106.17 136.88,106.39 136.88,107.72 140.93,111.76 185.3,111.76 187.54,109.52 187.54,107.33 v1(187.15,106.94)
DQD-3: length 66
  TOP w0.102: U1.W12 185.27,107.6 v1(185.84,108.17) ; U5.B23 v1(136.73,103.76)
  SIG1 w0.102: v1(136.73,103.76) 137.13,103.76 137.73,104.36 139.25,104.36 140.42,105.52 140.42,106.63 140.32,106.73 138.9,106.73 138.68,106.95 138.68,107.32 138.9,107.54 140.41,107.54 140.51,107.64 140.51,107.85 140.41,107.95 138.9,107.95 138.68,108.17 138.68,108.54 138.9,108.76 140.32,108.76 140.42,108.86 140.42,110.03 141.46,111.07 185.23,111.07 186.76,109.54 186.76,109.09 185.84,108.18 v1(185.84,108.17)
DQD-4: length 65.9
  TOP w0.102: v1(185.84,105.63) 185.27,105.05 U1.U12 ; U5.B20 133.22,103.25 v1(132.72,103.76)
  SIG2 w0.102: v1(132.72,103.76) 132.32,104.16 132.32,105.13 139.44,112.25 183.79,112.25 186.33,109.71 186.33,107.69 186,107.36 185.71,107.36 185.45,107.09 185.45,106.74 185.84,106.34 v1(185.84,105.63)
DQD-5: length 65.8
  TOP w0.102: v1(133.72,103.76) 133.72,103.75 134.22,103.25 U5.B21 ; U1.V13 184.03,106.32 v1(184.66,106.95)
  SIG2 w0.102: v1(184.66,106.95) 184.66,107.51 184.15,108.02 184.15,108.33 184.42,108.61 184.42,110.23 182.97,111.68 140.59,111.68 139.98,111.07 139.98,107.3 139.56,106.88 138.92,106.88 138.7,107.1 138.7,108.19 138.6,108.29 138.4,108.29 138.3,108.19 138.3,107.1 138.08,106.88 135.09,106.88 133.32,105.11 133.32,104.16 133.72,103.76 v1(133.72,103.76)
DQD-6: length 66
  TOP w0.102: v1(182.15,108.19) 182.15,108.17 182.73,107.59 U1.W14 ; v1(138.73,102.76) 138.22,102.25 U5.C25
  SIG1 w0.102: v1(138.73,102.76) 139.26,102.76 139.59,102.42 140.09,102.42 142.47,104.8 142.47,107.27 142.66,107.45 142.91,107.45 143.01,107.35 143.01,104.9 143.23,104.68 143.6,104.68 143.83,104.9 143.83,107.35 143.93,107.45 144.13,107.45 144.23,107.35 144.23,104.9 144.45,104.68 144.82,104.68 145.04,104.9 145.04,107.35 145.15,107.45 145.35,107.45 145.45,107.35 145.45,104.9 145.67,104.68 146.04,104.68 146.26,104.9 146.26,107.24 146.37,107.34 147.41,107.34 147.77,107.7 147.77,108.61 147.94,108.78 178.52,108.78 179.81,107.48 181.44,107.48 v1(182.15,108.19)
DQD-7: length 66
  TOP w0.102: U5.D19 v1(132.73,101.75) ; U1.U14 v1(182.1,105.68)
  SIG2 w0.102: v1(182.1,105.68) 183.54,107.13 183.54,109.68 182.03,111.19 143.11,111.19 142.89,110.97 142.89,110.63 142.78,110.53 142.58,110.53 142.48,110.63 142.48,110.97 142.26,111.19 141.51,111.19 140.69,110.37 140.69,106.94 139.82,106.07 135.07,106.07 134.12,105.12 134.12,102.54 133.93,102.36 133.33,102.36 v1(132.73,101.75)
DQD-8: length 65.9
  TOP w0.102: v1(135.73,102.76) 135.22,102.25 U5.C22 ; U1.V15 v1(180.88,106.9)
  SIG2 w0.102: v1(180.88,106.9) 180.9,106.9 181,107 181,107.33 181.1,107.43 182.56,107.43 182.89,107.75 182.89,108.53 182.48,108.94 147.75,108.94 146.97,108.16 146.97,104.34 146.2,103.57 145.08,103.57 144.98,103.67 144.98,105.76 144.76,105.98 144.39,105.98 144.17,105.76 144.17,103.67 144.07,103.57 143.87,103.57 143.76,103.67 143.76,105.76 143.54,105.98 143.17,105.98 142.95,105.76 142.95,103.67 142.85,103.57 139.41,103.57 139.2,103.36 136.34,103.36 135.74,102.76 v1(135.73,102.76)
DQD-9: length 65.9
  TOP w0.102: v1(180.67,109.89) 180.67,108.67 180.19,108.19 U1.W16 ; v1(136.74,102.76) 136.23,102.25 U5.C23
  SIG1 w0.102: v1(136.74,102.76) 136.95,102.76 137.35,103.15 139.34,103.15 139.98,103.79 140.29,103.79 141.58,105.08 141.58,109.45 142.08,109.94 142.33,109.94 142.43,109.84 142.43,108.33 142.65,108.11 143.02,108.11 143.24,108.33 143.24,109.84 143.34,109.94 143.54,109.94 143.65,109.84 143.65,108.33 143.87,108.11 144.24,108.11 144.46,108.33 144.46,109.84 144.56,109.94 144.76,109.94 144.87,109.84 144.87,108.33 145.09,108.11 145.46,108.11 145.68,108.33 145.68,109.84 145.78,109.94 145.98,109.94 146.08,109.84 146.08,108.33 146.3,108.11 146.68,108.11 146.9,108.33 146.9,109.84 146.98,109.93 180.63,109.93 v1(180.67,109.89)
DQD-10: length 66
  TOP w0.102: U1.V16 180.19,106.32 v1(179.58,105.71) ; U5.C24 v1(137.73,102.76)
  SIG2 w0.102: v1(137.73,102.76) 138.13,102.36 147.57,102.36 148.19,102.98 148.19,107.3 148.89,108.01 167.88,108.01 168.1,107.79 168.1,106.48 168.2,106.38 168.4,106.38 168.5,106.48 168.5,107.79 168.72,108.01 169.09,108.01 169.32,107.79 169.32,106.48 169.42,106.38 169.62,106.38 169.72,106.48 169.72,107.79 169.94,108.01 170.31,108.01 170.53,107.79 170.53,106.48 170.64,106.38 170.84,106.38 170.94,106.48 170.94,107.79 171.16,108.01 171.53,108.01 171.75,107.79 171.75,106.48 171.86,106.38 172.06,106.38 172.16,106.48 172.16,107.79 172.38,108.01 172.75,108.01 172.97,107.79 172.97,106.48 173.07,106.38 173.28,106.38 173.38,106.48 173.38,107.79 173.6,108.01 179.97,108.01 180.3,107.68 180.3,106.43 v1(179.58,105.71)
DQD-11: length 65.9
  TOP w0.102: U1.Y19 v1(175.76,109.49) ; U5.D21 v1(134.73,101.75)
  SIG2 w0.102: v1(134.73,101.75) 134.88,101.9 134.88,102.79 136.25,104.16 141.65,104.16 142.13,104.63 142.13,108.56 143.88,110.31 144.14,110.31 144.24,110.21 144.24,107.29 144.46,107.07 144.83,107.07 145.05,107.29 145.05,110.21 145.15,110.31 145.35,110.31 145.46,110.21 145.46,107.29 145.68,107.07 146.05,107.07 146.27,107.29 146.27,110.21 146.37,110.31 177.45,110.31 177.89,109.87 177.89,109.67 177.7,109.49 v1(175.76,109.49)
ECE: length 82.7
  TOP w0.14: J4.8 171.33,145.27 170.06,144 R46.2
  SIG2 w0.152: v1(196.09,90.47) 196.71,91.09 196.71,133.84 191.25,139.31 173.84,139.31 172.61,140.54 172.61,144 J4.8
  BOTTOM w0.14: R4.1 196.1,90.47 v1(196.09,90.47)
ENABLE1: length 58.8
  TOP w0.305: U23.19 92.94,159.33 92.95,159.33 92.95,158.46 v1(92.95,158.45)
  BOTTOM w0.305: 96.19,188.93 96.19,161.69 v1(92.95,158.45) ; 96.19,188.93 105.99,188.93 106.63,188.29 106.63,185.73 107.62,184.74 R96.2 ; 96.19,188.93 96.19,189.5 95.53,190.16 J14.2 90.29,188.89 R120.1
ENABLE2: length 51.5
  TOP w0.305: U16.2 132.58,194.57 v1(132.58,194.57) ; v2(93.16,191.71) 93.16,189.22 J14.4
  BOTTOM w0.305: J14.4 90.29,186.35 R121.1 ; v2(93.16,191.71) 97.51,191.71 99.71,193.91 125.22,193.91 125.88,194.57 v1(132.58,194.57)
ENABLE3: length 135
  TOP w0.305: 183.66,207.82 169.47,207.82 168.35,206.69 ; 183.66,207.82 198.61,207.82 200.19,206.24 U18.8 ; 183.66,207.82 U20.8 ; v2(94.82,192.81) 94.82,188.34 J14.6 ; v2(168.35,206.73) 168.35,206.69 ; 168.35,206.69 U22.8
  BOTTOM w0.305: J14.6 90.29,183.81 R122.1 ; v2(94.82,192.81) 102.89,200.88 145.47,200.88 151.32,206.73 v2(168.35,206.73)
ENABLE26400: length 8.5
  TOP w0.305: U13.3 108.76,187.37 v1(108.54,187.14) 108.14,186.75 C177.1 ; v1(110.71,187.12) 110.71,187.12 U13.6
  BOTTOM w0.305: R96.1 108.14,186.74 v1(108.54,187.14) 108.54,187.5 108.88,187.84 110.37,187.84 110.71,187.5 v1(110.71,187.12)
EXT_TRIG+: length 126.6
  TOP w0.102: R136.2 199.52,179.44 199.42,179.54 199.42,179.9 199.27,180.05 198.33,180.05 198.33,180.05 ; U5.G18 131.22,98.26 v1(131.72,98.75) ; 198.33,180.05 198.32,180.05 184.64,180.05 156.33,151.73 147,151.73 131.36,136.09 131.36,109.17 v1(131.72,108.81) ; 198.33,180.05 R137.1
  SIG2 w0.102: v1(131.72,98.75) 131.32,99.15 131.32,108.41 v1(131.72,108.81)
EXT_TRIG-: length 127.1
  TOP w0.102: R134.2 200.08,180.97 199.57,180.97 199.47,180.87 199.47,180.49 199.28,180.3 198.34,180.3 198.33,180.32 ; v1(130.72,98.75) 130.22,98.26 U5.G17 ; 198.33,180.32 198.31,180.3 184.54,180.3 156.22,151.99 146.9,151.99 131.1,136.19 131.1,109.2 v1(130.72,108.81) ; 198.33,180.32 R135.1
  SIG2 w0.102: v1(130.72,98.75) 131.11,99.15 131.11,108.41 v1(130.72,108.81)
FIFOADR0: length 61.1
  TOP w0.102: v1(118.71,81.74) 118.71,81.74 U5.AC6
  TOP w0.14: U2.89 103.8,37.27 104.88,38.35 104.88,76.26 v1(105.23,76.61)
  BOTTOM w0.14: v1(105.23,76.61) 109.88,81.25 118.24,81.25 118.71,81.72 v1(118.71,81.74)
FIFOADR1: length 61.1
  TOP w0.102: U5.AB6 118.71,82.74 v1(118.71,82.74)
  TOP w0.14: U2.90 103.1,37.77 104.43,39.1 v1(104.43,76.62)
  BOTTOM w0.14: v1(104.43,76.62) 110.07,82.26 118.22,82.26 v1(118.71,82.74)
FLAGA: length 76.7
  TOP w0.102: v1(122.71,84.74) 123.21,85.24 U5.Y10
  TOP w0.14: U2.69 v1(109.76,27.27)
  SIG2 w0.152: v1(122.71,84.74) 123.21,84.24 123.21,74.59 115.24,66.61 115.24,29.41 113.09,27.27 v1(109.76,27.27)
FLAGB: length 74.4
  TOP w0.102: v1(122.71,83.74) 123.21,84.24 U5.AA10
  TOP w0.14: U2.70 v1(108.56,27.77)
  SIG2 w0.152: v1(122.71,83.74) 122.71,83.34 122.23,82.86 122.23,74.37 114.93,67.08 114.93,67.06 114.43,66.56 114.43,29.75 112.45,27.77 v1(108.56,27.77)
FLAGC: length 70.9
  TOP w0.102: U5.AC7 120.22,82.25 119.71,81.74 v1(119.71,81.74)
  TOP w0.14: v1(113.62,30.27) 111.63,28.27 U2.71
  SIG2 w0.152: v1(119.71,81.74) 120.23,81.22 120.23,77.6 113.62,70.99 113.62,59.78 113.92,59.48 113.92,59.13 113.62,58.84 v1(113.62,30.27)
FLASH_TDO: length 77.5
  TOP w0.102: v1(125.71,84.74) 125.22,85.23 U5.Y12
  TOP w0.14: v1(151.42,36.45) 151.53,36.35 U14.22 ; v1(144.93,59.75) R43.2
  SIG1 w0.152: v1(144.9,70.96) 130.22,70.96 125.22,75.96 125.22,84.25 v1(125.71,84.74)
  SIG3 w0.152: v1(151.42,36.45) 151.42,49.18 145.77,54.83 145.77,58.91 v1(144.93,59.75) 144.9,59.79 v1(144.9,70.96)
FMC_CALRUN: length 110.7
  TOP w0.102: v1(118.72,96.74) U5.H6
  TOP w0.152: v3(83.87,95.33) 56.24,95.33 53.7,92.79 v3(14.61,92.79)
  BOTTOM w0.102: FMC.G18 v3(14.61,92.79)
  BOTTOM w0.152: v1(118.72,96.74) 118.21,96.24 118.21,93.45 118.01,93.24 85.95,93.24 v3(83.87,95.33)
FMC_DCLK_DI+: length 142.1
  TOP w0.102: v1(114.72,95.75) U5.J2
  SIG3 w0.102: v3(86.41,95.33) 86.41,96.01 86.59,96.19 86.92,96.19 87.97,95.14 114.11,95.14 v1(114.72,95.75)
  BOTTOM w0.102: v3(86.41,95.33) 86.21,95.53 86.21,102.06 72.5,115.77 9.78,115.77 9.4,115.4 9.4,95.6 9.8,95.2 10.92,95.2 FMC.D20
FMC_DCLK_DI-: length 142.1
  TOP w0.102: v1(113.72,95.75) U5.J1
  SIG3 w0.102: v3(85.75,95.33) 86.21,95.78 86.21,96.1 86.5,96.39 87,96.39 88.05,95.34 114.03,95.34 114.22,95.54 114.22,96.06 114.12,96.16 113.84,96.16 113.72,96.05 v1(113.72,95.75)
  BOTTOM w0.102: v3(85.75,95.33) 85.95,95.53 85.95,101.96 72.39,115.52 9.88,115.52 9.65,115.29 9.65,95.71 9.91,95.45 10.92,95.45 FMC.D21
FMC_DCLK_DID+: length 142.1
  TOP w0.102: v1(120.71,90.75) 121.2,91.24 U5.P8
  SIG3 w0.102: v1(120.71,90.75) 120.71,91.06 120.83,91.19 121.01,91.19 121.18,91.01 121.18,90.55 119.98,89.35 76.95,89.35 59.53,71.93 54.28,71.93 54.18,72.03 54.18,72.83 53.96,73.05 53.59,73.05 53.37,72.83 53.37,72.03 53.27,71.93 53.07,71.93 52.96,72.03 52.96,72.83 52.74,73.05 52.37,73.05 52.15,72.83 52.15,72.03 52.05,71.93 51.85,71.93 51.74,72.03 51.74,72.83 51.52,73.05 51.15,73.05 50.93,72.83 50.93,72.03 50.83,71.93 50.63,71.93 50.53,72.03 50.53,72.83 50.3,73.05 49.93,73.05 49.71,72.83 49.71,72.03 49.61,71.93 49.41,71.93 49.31,72.03 49.31,72.83 49.09,73.05 48.71,73.05 48.49,72.83 48.49,72.03 48.39,71.93 48.19,71.93 48.09,72.03 48.09,72.86 47.87,73.08 47.49,73.08 47.27,72.86 47.27,72.03 47.17,71.93 11.6,71.93 11.53,72.01 11.53,76.78 11.57,76.81 16.23,76.81 16.38,76.66 16.38,76.45 16.21,76.28 v3(15.88,76.28)
  BOTTOM w0.102: FMC.G6 v3(15.88,76.28)
FMC_DCLK_DID-: length 142.1
  TOP w0.102: v1(120.71,91.75) 121.2,92.25 U5.N8
  SIG3 w0.102: v3(15.88,77.55) 15.34,77.01 11.48,77.01 11.33,76.86 11.33,71.92 11.52,71.73 47.26,71.73 47.48,71.95 47.48,72.77 47.58,72.87 47.78,72.87 47.88,72.77 47.88,71.95 48.1,71.73 48.48,71.73 48.7,71.95 48.7,72.75 48.8,72.85 49,72.85 49.1,72.75 49.1,71.95 49.32,71.73 49.7,71.73 49.92,71.95 49.92,72.75 50.02,72.85 50.22,72.85 50.32,72.75 50.32,71.95 50.54,71.73 50.91,71.73 51.14,71.95 51.14,72.75 51.24,72.85 51.44,72.85 51.54,72.75 51.54,71.95 51.76,71.73 52.13,71.73 52.35,71.95 52.35,72.75 52.46,72.85 52.66,72.85 52.76,72.75 52.76,71.95 52.98,71.73 53.35,71.73 53.57,71.95 53.57,72.75 53.68,72.85 53.88,72.85 53.98,72.75 53.98,71.95 54.2,71.73 59.61,71.73 77.03,89.15 120.07,89.15 121.39,90.47 121.39,91.09 120.73,91.75 v1(120.71,91.75)
  BOTTOM w0.102: FMC.G7 v3(15.88,77.55)
FMC_DCLK_DQ+: length 142.1
  TOP w0.102: v1(114.72,96.74) U5.H2
  SIG3 w0.102: v3(78.13,92.79) 78.17,92.79 82.73,97.34 114.12,97.34 v1(114.72,96.74)
  BOTTOM w0.102: FMC.K25 19.56,101.55 50.39,101.55 50.64,101.8 50.64,103.23 50.74,103.33 50.95,103.33 51.05,103.23 51.05,101.8 51.3,101.55 51.71,101.55 51.96,101.8 51.96,103.23 52.06,103.33 52.27,103.33 52.37,103.23 52.37,101.8 52.62,101.55 53.03,101.55 53.28,101.8 53.28,103.23 53.39,103.33 53.59,103.33 53.69,103.23 53.69,101.8 53.94,101.55 54.35,101.55 54.6,101.8 54.6,103.23 54.71,103.33 54.91,103.33 55.01,103.23 55.01,101.8 55.26,101.55 55.68,101.55 55.93,101.8 55.93,103.23 56.03,103.33 56.23,103.33 56.33,103.23 56.33,101.8 56.58,101.55 57,101.55 57.25,101.8 57.25,103.23 57.35,103.33 57.55,103.33 57.65,103.23 57.65,101.8 57.9,101.55 58.32,101.55 58.57,101.8 58.57,103.25 58.67,103.35 58.87,103.35 58.97,103.25 58.97,101.8 59.22,101.55 59.64,101.55 59.89,101.8 59.89,103.25 59.99,103.35 60.19,103.35 60.29,103.25 60.29,101.8 60.54,101.55 60.96,101.55 61.21,101.8 61.21,103.25 61.31,103.35 61.51,103.35 61.62,103.25 61.62,101.8 61.87,101.55 62.28,101.55 62.53,101.8 62.53,103.25 62.63,103.35 62.83,103.35 62.94,103.25 62.94,101.8 63.19,101.55 63.6,101.55 63.85,101.8 63.85,103.25 63.95,103.35 64.16,103.35 64.26,103.25 64.26,101.8 64.51,101.55 77.5,101.55 78.33,100.71 78.33,92.99 v3(78.13,92.79)
FMC_DCLK_DQ-: length 142.1
  TOP w0.102: v1(113.72,96.74) U5.H1
  SIG3 w0.102: v3(78.79,92.79) 78.79,93.12 82.81,97.14 114.04,97.14 114.25,96.93 114.25,96.93 114.25,96.8 114.1,96.65 113.82,96.65 v1(113.72,96.74)
  BOTTOM w0.102: FMC.K26 19.56,101.8 50.29,101.8 50.39,101.9 50.39,103.33 50.64,103.58 51.05,103.58 51.3,103.33 51.3,101.9 51.4,101.8 51.61,101.8 51.71,101.9 51.71,103.33 51.96,103.58 52.37,103.58 52.62,103.33 52.62,101.9 52.73,101.8 52.93,101.8 53.03,101.9 53.03,103.33 53.28,103.58 53.69,103.58 53.94,103.33 53.94,101.9 54.05,101.8 54.25,101.8 54.35,101.9 54.35,103.33 54.6,103.58 55.01,103.58 55.27,103.33 55.27,101.9 55.37,101.8 55.57,101.8 55.67,101.9 55.67,103.33 55.92,103.58 56.34,103.58 56.59,103.33 56.59,101.9 56.69,101.8 56.89,101.8 56.99,101.9 56.99,103.33 57.24,103.58 57.66,103.58 57.91,103.33 57.91,101.9 58.01,101.8 58.21,101.8 58.31,101.9 58.31,103.36 58.56,103.61 58.98,103.61 59.23,103.36 59.23,101.9 59.33,101.8 59.53,101.8 59.63,101.9 59.63,103.36 59.88,103.61 60.3,103.61 60.55,103.36 60.55,101.9 60.65,101.8 60.85,101.8 60.95,101.9 60.95,103.36 61.2,103.61 61.62,103.61 61.87,103.36 61.87,101.9 61.97,101.8 62.17,101.8 62.28,101.9 62.28,103.36 62.53,103.61 62.94,103.61 63.19,103.36 63.19,101.9 63.29,101.8 63.49,101.8 63.6,101.9 63.6,103.36 63.85,103.61 64.26,103.61 64.51,103.36 64.51,101.9 64.61,101.8 77.6,101.8 78.59,100.82 78.59,92.99 v3(78.79,92.79)
